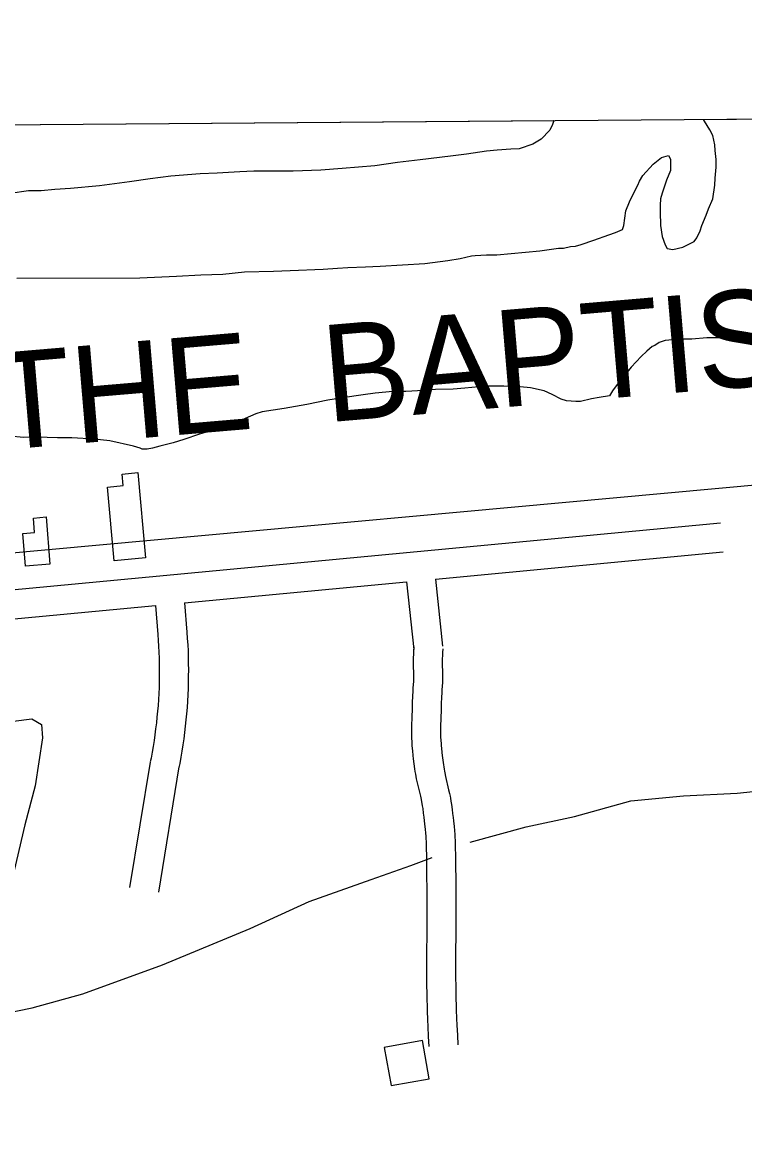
# Model space of a CAD drawing. Extents: x 3535183 to 3573198, y 534952 to 560562.
# Drawn here: x 3556934 to 3557679, y 557626 to 558775 of the extents above; entities that cross this region are included whole.
import ezdxf

# ---------------------------------------------------------------- set-up
doc = ezdxf.new("R2010")
doc.units = 0
for name, color, linetype in [('V-BLDG-OTLN', 7, 'Continuous'), ('V-GRID-FRAM', 7, 'Continuous'), ('V-ROAD-CNTR', 7, 'Continuous'), ('V-SITE-VEGE', 7, 'Continuous'), ('V-TOPO-BNDY', 7, 'Continuous'), ('V-TOPO-GNAM-IDEN', 7, 'Continuous'), ('V-TOPO-SHOR', 7, 'Continuous')]:
    doc.layers.add(name, color=color, linetype=linetype)

msp = doc.modelspace()

# ---------------------------------------------------------------- linework, layer by layer
at = {"layer": 'V-BLDG-OTLN'}
for points in [[(3557052.7, 558310.2), (3557060.7, 558222.1), (3557028.3, 558219.2), (3557021.4, 558295.2), (3557037.5, 558296.7), (3557036.5, 558308.4)], [(3556958, 558264.5), (3556961.9, 558215.5), (3556936.8, 558213.5), (3556934.1, 558247.4), (3556946.1, 558248.3), (3556945, 558263.1)], [(3557314, 557677.8), (3557353.4, 557684.8), (3557346.4, 557724.2), (3557307, 557717.1)]]:
    msp.add_lwpolyline(points, close=True, dxfattribs=at)
at = {"layer": 'V-GRID-FRAM'}
msp.add_lwpolyline([(3539245.8, 558535.3), (3570887.5, 558774.6), (3571033, 540592.1), (3539375.4, 540352.7), (3539245.8, 558535.3)], dxfattribs=at)
at = {"layer": 'V-ROAD-CNTR'}
for points in [[(3555805.2, 558083.6), (3557653.8, 558258.1)], [(3557359.8, 558200.2), (3557656.7, 558228.3)], [(3557100.8, 558175.8), (3557329.9, 558197.4)], [(3557329.9, 558197.4), (3557337.4, 558127.7)], [(3557359.8, 558200.2), (3557367.2, 558130.9)], [(3555807.3, 558053.7), (3557070.9, 558173)], [(3557070.9, 558173), (3557073.4, 558143.1)], [(3557100.8, 558175.8), (3557103.3, 558145.5)], [(3557073.4, 558143.2), (3557073.8, 558137), (3557074.2, 558130.9), (3557074.5, 558124.9), (3557074.7, 558118.8), (3557074.8, 558112.7), (3557074.9, 558106.6), (3557074.8, 558100.5), (3557074.7, 558094.4), (3557074.6, 558088.3), (3557074.3, 558082.2), (3557074, 558076.1), (3557073.6, 558070), (3557073.1, 558063.9), (3557072.5, 558057.8), (3557071.9, 558051.8), (3557071.1, 558045.7), (3557070.3, 558039.7), (3557069.5, 558033.6), (3557068.5, 558027.6), (3557067.5, 558021.6), (3557066.4, 558015.6), (3557065.6, 558011.7)], [(3557103.3, 558145.4), (3557103.8, 558139), (3557104.2, 558132.5), (3557104.5, 558126.1), (3557104.7, 558119.6), (3557104.8, 558113.1), (3557104.9, 558106.6), (3557104.8, 558100.2), (3557104.7, 558093.7), (3557104.5, 558087.2), (3557104.3, 558080.7), (3557103.9, 558074.3), (3557103.5, 558067.8), (3557103, 558061.3), (3557102.4, 558054.9), (3557101.7, 558048.4), (3557100.9, 558042), (3557100.1, 558035.6), (3557099.1, 558029.2), (3557098.1, 558022.8), (3557097, 558016.4), (3557095.9, 558010), (3557095.1, 558006)], [(3557337.3, 558130.2), (3557337.1, 558126.2), (3557337, 558123.1), (3557336.8, 558118.5), (3557336.7, 558113.9), (3557336.8, 558111.7), (3557336.8, 558109.7), (3557337.1, 558104), (3557337.2, 558102.9), (3557337.2, 558101.1), (3557337.2, 558100.4), (3557337.2, 558099.6), (3557337, 558095), (3557336.6, 558087.8), (3557336.4, 558084.1), (3557336.2, 558080.3), (3557335.8, 558072.4), (3557335.6, 558066.5), (3557335.3, 558057.7), (3557335, 558048.7), (3557335, 558045.9), (3557335, 558043.3), (3557335, 558040.8), (3557335, 558038.4), (3557335.1, 558036.2), (3557335.3, 558032.2), (3557335.5, 558028.7), (3557335.8, 558025.6), (3557336, 558022.9), (3557336.5, 558018.3), (3557336.9, 558014.8), (3557337.5, 558009.7), (3557338.2, 558004.5), (3557338.6, 558001.7), (3557339.1, 557999), (3557339.6, 557996.5), (3557340, 557994.2), (3557340.9, 557990), (3557344.2, 557976.2), (3557344.9, 557973), (3557345.4, 557970.6), (3557345.7, 557968.9), (3557346.2, 557966.2), (3557346.6, 557963.6), (3557347.2, 557958.8), (3557347.8, 557954.5), (3557348.2, 557950.8), (3557348.6, 557947.6), (3557348.9, 557944.8), (3557349.1, 557942.4), (3557349.5, 557938.1), (3557349.8, 557935), (3557349.9, 557932.6), (3557350.1, 557929.1), (3557350.2, 557925.6), (3557350.5, 557911.6), (3557350.6, 557901), (3557350.7, 557893.1), (3557350.8, 557881.3), (3557350.9, 557869.4), (3557350.9, 557858.4), (3557350.8, 557839.1), (3557350.6, 557810.1), (3557350.6, 557795.5), (3557350.6, 557788.2), (3557350.7, 557780.9), (3557350.8, 557773), (3557350.9, 557766.1), (3557351.1, 557760.1), (3557351.3, 557754.8), (3557351.6, 557745.6), (3557351.9, 557738.7), (3557352.4, 557728.4), (3557353, 557718.2)], [(3557367.3, 558128.3), (3557367.1, 558124.6), (3557366.9, 558121.9), (3557366.8, 558117.8), (3557366.7, 558113.8), (3557366.8, 558112.3), (3557366.8, 558111), (3557367.1, 558105.4), (3557367.2, 558103.8), (3557367.2, 558101.3), (3557367.2, 558099.9), (3557367.2, 558098.6), (3557366.9, 558093.5), (3557366.5, 558086.1), (3557366.3, 558082.4), (3557366.1, 558078.9), (3557365.8, 558071.2), (3557365.6, 558065.4), (3557365.2, 558056.7), (3557365, 558048.1), (3557365, 558045.7), (3557365, 558043.4), (3557365, 558041.3), (3557365, 558039.3), (3557365.1, 558037.5), (3557365.3, 558033.9), (3557365.5, 558030.8), (3557365.7, 558028.1), (3557365.9, 558025.8), (3557366.3, 558021.5), (3557366.7, 558018.3), (3557367.3, 558013.5), (3557367.9, 558008.7), (3557368.3, 558006.4), (3557368.6, 558004.3), (3557369, 558002.2), (3557369.4, 558000.3), (3557370.2, 557996.6), (3557373.4, 557982.9), (3557374.2, 557979.2), (3557374.8, 557976.4), (3557375.2, 557974.3), (3557375.8, 557971), (3557376.3, 557967.8), (3557376.9, 557962.7), (3557377.5, 557958.3), (3557378, 557954.4), (3557378.4, 557950.9), (3557378.7, 557947.9), (3557379, 557945.2), (3557379.4, 557940.6), (3557379.7, 557937), (3557379.9, 557934.3), (3557380.1, 557930.3), (3557380.2, 557926.3), (3557380.5, 557912.1), (3557380.6, 557901.4), (3557380.7, 557893.4), (3557380.8, 557881.5), (3557380.9, 557869.5), (3557380.9, 557858.4), (3557380.8, 557839), (3557380.6, 557810), (3557380.6, 557795.5), (3557380.6, 557788.3), (3557380.7, 557781.2), (3557380.8, 557773.5), (3557380.9, 557766.8), (3557381.1, 557761), (3557381.3, 557755.9), (3557381.6, 557746.8), (3557381.9, 557740.1), (3557382.4, 557729.9), (3557382.9, 557719.7)], [(3557065.6, 558011.3), (3557044.3, 557882.1)], [(3557095.2, 558006.5), (3557073.9, 557877.2)]]:
    msp.add_lwpolyline(points, dxfattribs=at)
at = {"layer": 'V-SITE-VEGE'}
for p, q in [((3557636.2, 558674.4), (3557976.9, 558677)), ((3555898.7, 558661.3), (3557481.9, 558673.2)), ((3557480.4, 558669.2), (3557477.8, 558663.5)), ((3557481.9, 558673.2), (3557480.4, 558669.2)), ((3557637.5, 558672.5), (3557636.2, 558674.4)), ((3557642.7, 558663.7), (3557637.5, 558672.5)), ((3557469, 558654.1), (3557460.2, 558648.9)), ((3557477.8, 558663.5), (3557469, 558654.1)), ((3557645.8, 558658), (3557642.7, 558663.7)), ((3557647.9, 558648.1), (3557645.8, 558658)), ((3557412.5, 558641.6), (3557391.7, 558638.5)), ((3557423.4, 558642.7), (3557412.5, 558641.6)), ((3557437.4, 558643.7), (3557423.4, 558642.7)), ((3557446.2, 558644.2), (3557437.4, 558643.7)), ((3557460.2, 558648.9), (3557446.2, 558644.2)), ((3557648.4, 558642.4), (3557647.9, 558648.1)), ((3557649.5, 558633.1), (3557648.4, 558642.4)), ((3557320.7, 558630.1), (3557297.4, 558626.4)), ((3557344, 558632.7), (3557320.7, 558630.1)), ((3557375.2, 558636.4), (3557344, 558632.7)), ((3557391.7, 558638.5), (3557375.2, 558636.4)), ((3557584.2, 558628.3), (3557593, 558635.1)), ((3557593, 558635.1), (3557600.2, 558637.2)), ((3557600.2, 558637.2), (3557602.3, 558633.5)), ((3557602.3, 558633.5), (3557602.3, 558621.6)), ((3557649.5, 558625.3), (3557649.5, 558633.1)), ((3557116.9, 558618.4), (3557086.8, 558615.8)), ((3557134.5, 558619), (3557116.9, 558618.4)), ((3557157.9, 558620.5), (3557134.5, 558619)), ((3557172.4, 558621.1), (3557157.9, 558620.5)), ((3557212.9, 558621.1), (3557172.4, 558621.1)), ((3557241.4, 558622.2), (3557212.9, 558621.1)), ((3557263.7, 558623.8), (3557241.4, 558622.2)), ((3557297.4, 558626.4), (3557263.7, 558623.8)), ((3557573.8, 558616.4), (3557584.2, 558628.3)), ((3557602.3, 558621.6), (3557598.2, 558611.8)), ((3557648.5, 558613.9), (3557649.5, 558625.3)), ((3557044.3, 558610), (3557013.2, 558605.8)), ((3557065.6, 558613.2), (3557044.3, 558610)), ((3557086.8, 558615.8), (3557065.6, 558613.2)), ((3557566.6, 558602.9), (3557568.6, 558606.5)), ((3557568.6, 558606.5), (3557570.2, 558610.7)), ((3557570.2, 558610.7), (3557573.8, 558616.4)), ((3557598.2, 558611.8), (3557593.5, 558598.3)), ((3557645.9, 558592.6), (3557648, 558606.6)), ((3557648, 558606.6), (3557648.5, 558613.9)), ((3556940.1, 558600.6), (3556920.9, 558597.9)), ((3556953.1, 558600.6), (3556940.1, 558600.6)), ((3556967.1, 558602.1), (3556953.1, 558600.6)), ((3556983.1, 558603.2), (3556967.1, 558602.1)), ((3557013.2, 558605.8), (3556983.1, 558603.2)), ((3557559.8, 558589.4), (3557566.6, 558602.9)), ((3557593.5, 558598.3), (3557592, 558592.6)), ((3557556.2, 558580.1), (3557559.8, 558589.4)), ((3557592, 558592.6), (3557591.5, 558585.8)), ((3557591.5, 558585.8), (3557591.5, 558579.1)), ((3557641.3, 558582.3), (3557645.9, 558592.6)), ((3557554.2, 558565), (3557556.2, 558580.1)), ((3557591.5, 558579.1), (3557592, 558565.1)), ((3557634.5, 558565.1), (3557639.2, 558575.5)), ((3557639.2, 558575.5), (3557641.3, 558582.3)), ((3557545.4, 558557.8), (3557552.6, 558560.9)), ((3557552.6, 558560.9), (3557554.2, 558565)), ((3557592, 558565.1), (3557593.6, 558553.7)), ((3557633, 558559.4), (3557634.5, 558565.1)), ((3557510.1, 558545.3), (3557523.1, 558549.9)), ((3557523.1, 558549.9), (3557538.6, 558555.2)), ((3557538.6, 558555.2), (3557545.4, 558557.8)), ((3557593.6, 558553.7), (3557596.7, 558544.9)), ((3557626.8, 558548.5), (3557629.4, 558552.2)), ((3557629.4, 558552.2), (3557633, 558559.4)), ((3557423, 558534.8), (3557467.6, 558539)), ((3557467.6, 558539), (3557486.8, 558541.6)), ((3557486.8, 558541.6), (3557492, 558541.6)), ((3557492, 558541.6), (3557499.2, 558543.2)), ((3557499.2, 558543.2), (3557504.4, 558543.7)), ((3557504.4, 558543.7), (3557510.1, 558545.3)), ((3557596.7, 558544.9), (3557598.8, 558541.2)), ((3557598.8, 558541.2), (3557604.5, 558540.2)), ((3557604.5, 558540.2), (3557614.9, 558542.8)), ((3557614.9, 558542.8), (3557626.8, 558548.5)), ((3557348.8, 558525.9), (3557372.7, 558529)), ((3557372.7, 558529), (3557385.1, 558531.1)), ((3557385.1, 558531.1), (3557397.1, 558533.7)), ((3557397.1, 558533.7), (3557400.7, 558534.2)), ((3557400.7, 558534.2), (3557412.6, 558534.8)), ((3557412.6, 558534.8), (3557423, 558534.8)), ((3557117.6, 558514.2), (3557140.4, 558514.7)), ((3557140.4, 558514.7), (3557162.7, 558517.3)), ((3557162.7, 558517.3), (3557192.8, 558517.9)), ((3557192.8, 558517.9), (3557209.9, 558518.4)), ((3557209.9, 558518.4), (3557244.1, 558520)), ((3557244.1, 558520), (3557258.6, 558521.1)), ((3557258.6, 558521.1), (3557269.5, 558521.6)), ((3557269.5, 558521.6), (3557287.7, 558522.2)), ((3557287.7, 558522.2), (3557302.7, 558523.2)), ((3557302.7, 558523.2), (3557348.8, 558525.9)), ((3556927.8, 558510.8), (3557054.8, 558511)), ((3557054.8, 558511), (3557092.7, 558512.6)), ((3557092.7, 558512.6), (3557117.6, 558514.2)), ((3557596.8, 558446.3), (3557590.6, 558444.2)), ((3557611.9, 558447.9), (3557596.8, 558446.3)), ((3557624.3, 558447.9), (3557611.9, 558447.9)), ((3557639.9, 558449), (3557624.3, 558447.9)), ((3557703.1, 558449), (3557639.9, 558449)), ((3557577.7, 558435.4), (3557572, 558429.7)), ((3557583.4, 558440.1), (3557577.7, 558435.4)), ((3557586, 558441.1), (3557583.4, 558440.1)), ((3557590.6, 558444.2), (3557586, 558441.1)), ((3557572, 558429.7), (3557561.6, 558418.8)), ((3557561.6, 558418.8), (3557546.1, 558399.6)), ((3557285.2, 558390.4), (3557264, 558387.3)), ((3557297.7, 558392), (3557285.2, 558390.4)), ((3557315.8, 558393.6), (3557297.7, 558392)), ((3557329.3, 558393.6), (3557315.8, 558393.6)), ((3557347.5, 558394.7), (3557329.3, 558393.6)), ((3557359.9, 558395.7), (3557347.5, 558394.7)), ((3557378.1, 558396.3), (3557359.9, 558395.7)), ((3557390, 558397.3), (3557378.1, 558396.3)), ((3557404.5, 558398.4), (3557390, 558397.3)), ((3557413.3, 558399.4), (3557404.5, 558398.4)), ((3557430.4, 558399.4), (3557413.3, 558399.4)), ((3557447, 558398.4), (3557430.4, 558399.4)), ((3557457.9, 558397.4), (3557447, 558398.4)), ((3557471.9, 558394.3), (3557457.9, 558397.4)), ((3557480.2, 558390.7), (3557471.9, 558394.3)), ((3557489.6, 558386), (3557480.2, 558390.7)), ((3557539.3, 558389.2), (3557528.5, 558387.6)), ((3557542.4, 558394.4), (3557539.3, 558389.2)), ((3557546.1, 558399.6), (3557542.4, 558394.4)), ((3557227.2, 558380.5), (3557203.8, 558376.3)), ((3557248.9, 558384.7), (3557227.2, 558380.5)), ((3557264, 558387.3), (3557248.9, 558384.7)), ((3557494.8, 558384), (3557489.6, 558386)), ((3557504.6, 558383.5), (3557494.8, 558384)), ((3557509.3, 558383.5), (3557504.6, 558383.5)), ((3557520.7, 558386.1), (3557509.3, 558383.5)), ((3557528.5, 558387.6), (3557520.7, 558386.1)), ((3557163.4, 558365.9), (3557147.3, 558358.6)), ((3557174.3, 558370.6), (3557163.4, 558365.9)), ((3557181, 558372.7), (3557174.3, 558370.6)), ((3557203.8, 558376.3), (3557181, 558372.7)), ((3557140.1, 558356.5), (3557126.6, 558352.9)), ((3557147.3, 558358.6), (3557140.1, 558356.5)), ((3556934.7, 558346.4), (3556920.7, 558347.5)), ((3556948.7, 558346.5), (3556934.7, 558346.4)), ((3556970, 558346), (3556948.7, 558346.5)), ((3556984.5, 558346), (3556970, 558346)), ((3557007.8, 558344.5), (3556984.5, 558346)), ((3557023.9, 558342.9), (3557007.8, 558344.5)), ((3557048.3, 558337.2), (3557023.9, 558342.9)), ((3557100.1, 558344.1), (3557089.3, 558340.9)), ((3557116.2, 558349.8), (3557100.1, 558344.1)), ((3557126.6, 558352.9), (3557116.2, 558349.8)), ((3557055, 558335.2), (3557048.3, 558337.2)), ((3557057.1, 558334.1), (3557055, 558335.2)), ((3557062.3, 558334.2), (3557057.1, 558334.1)), ((3557068, 558335.2), (3557062.3, 558334.2)), ((3557075.3, 558337.3), (3557068, 558335.2)), ((3557089.3, 558340.9), (3557075.3, 558337.3))]:
    msp.add_line(p, q, dxfattribs=at)
at = {"layer": 'V-TOPO-BNDY'}
msp.add_line((3554702, 558025.1), (3560298.9, 558535.1), dxfattribs=at)
at = {"layer": 'V-TOPO-SHOR'}
for points in [[(3557395.7, 557929), (3557453.4, 557944.7), (3557503.2, 557955.3), (3557561.3, 557971.5), (3557615.6, 557976.7), (3557671, 557979.5), (3557726.8, 557985.2), (3557781.6, 557990.5), (3557820.5, 558000.5), (3557879.5, 558023.6), (3557929.7, 558046.1), (3557974.8, 558073.9), (3558013.5, 558094.3), (3558062.7, 558115.7), (3558131.5, 558144.9), (3558189.9, 558172.5), (3558213.1, 558181.7), (3558255.4, 558196.7), (3558277.1, 558199.5), (3558291, 558195.7), (3558300.5, 558186.4), (3558309, 558180.6)], [(3556907.8, 558051.5), (3556943.3, 558056), (3556953.3, 558050.2), (3556954.5, 558036.4), (3556946.8, 557986.8), (3556936, 557946.6), (3556917.9, 557868.7)], [(3556913.6, 557751.9), (3556943.7, 557757.8), (3556995.9, 557772.4), (3557078.1, 557802.2), (3557168.5, 557839.7), (3557229.5, 557867.7), (3557293.4, 557890.4), (3557334.3, 557904.9), (3557356.4, 557913.1)]]:
    msp.add_lwpolyline(points, dxfattribs=at)

# ---------------------------------------------------------------- texts
at = {"layer": 'V-TOPO-GNAM-IDEN'}
msp.add_text('ST.  JOHN THE  BAPTIST  PARISH', height=100, rotation=4.855, dxfattribs=at).set_placement((3556226, 558275.1))

doc.saveas('drawing.dxf')
